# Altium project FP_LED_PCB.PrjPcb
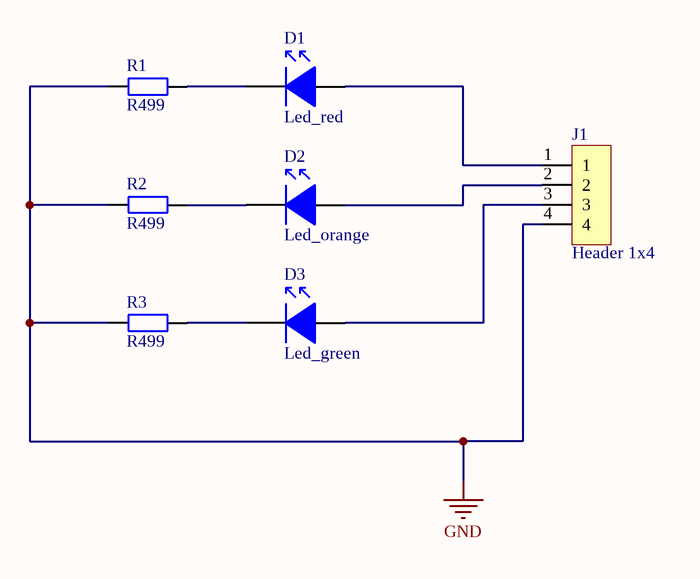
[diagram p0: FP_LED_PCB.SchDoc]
1 sheet, 7 parts. Net scope: global (net labels, ports and power ports of the same name join across sheets).
Board file: FP_LED_PCB.PcbDoc

## Sheet FP_LED_PCB.SchDoc
size A4; SheetNumber: 1; SheetTotal: 1

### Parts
D1  Led_red  [led_red_10mm]
D2  Led_orange  [led_orange_10mm]
D3  Led_green  [led_green_10mm]
J1  Header 1x4  [HDR4X1_FEMALE]
R1  R499  [RES1206]
R2  R499  [RES1206]
R3  R499  [RES1206]

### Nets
GND: J1.4 R1.1 R2.1 R3.1
NetD1_1: D1.1 R1.2
NetD1_2: D1.2 J1.1
NetD2_1: D2.1 R2.2
NetD2_2: D2.2 J1.2
NetD3_1: D3.1 R3.2
NetD3_2: D3.2 J1.3

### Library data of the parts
D1 = Led_red: 1206
D2 = Led_orange: 1206
D3 = Led_green: 1206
